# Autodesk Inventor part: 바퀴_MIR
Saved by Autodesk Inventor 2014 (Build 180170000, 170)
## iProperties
Created: 2015-05
Part Number: 바퀴_MIR
Material: 일반
Vendor: CBT Solutions
Document SubType Name: 모델링
Designer: Administrator
Appearance: 기본값
Company: 한국ATC센터
Author: KYOUNG IL JANG
Comments: 파생
d0: 1.000 ul
d0_1: 1.000 ul
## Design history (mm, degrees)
derived "바퀴.ipt" dims count "d0" = 1
feature "솔리드1::바퀴.ipt" dims count "d0" = 1
tag "피쳐 태그1"
node "솔리드1"
other parameters: "d0_1" = 1
